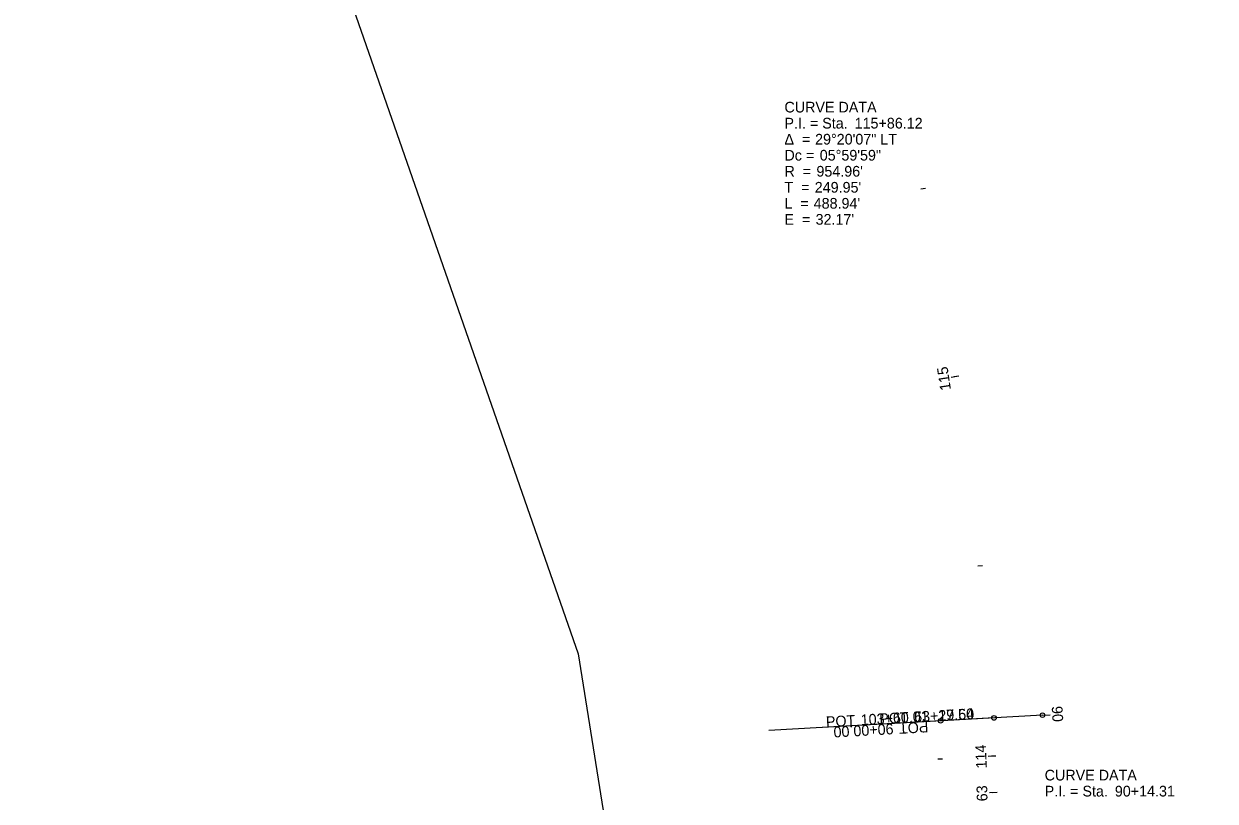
# Model space of a CAD drawing. Extents: x 1564517 to 1565226, y 635740 to 637455.
# Drawn here: x 1564517 to 1564828.9, y 636838.2 to 637041.9 of the extents above; entities that cross this region are included whole.
import ezdxf

# ---------------------------------------------------------------- set-up
doc = ezdxf.new("R2010")
doc.units = 0
for name, color, linetype in [('GK_Drainage_Nodes', 7, 'Continuous'), ('SC_Scratch10', 7, 'Continuous'), ('TX_P_1000', 7, 'Continuous'), ('UT_P_Water', 7, 'Continuous'), ('UT_P_Water_Cells', 7, 'Continuous'), ('UT_X_Electric', 7, 'Continuous'), ('UT_X_Sanitary_Pressure_Line', 7, 'Continuous'), ('UT_X_Water_Cells', 7, 'Continuous')]:
    doc.layers.add(name, color=color, linetype=linetype)

msp = doc.modelspace()

# ---------------------------------------------------------------- linework, layer by layer
at = {"layer": 'TX_P_1000'}
msp.add_line((1564771.02, 636860.06), (1564726.09, 636857.57), dxfattribs=at)
at = {"layer": 'UT_P_Water_Cells'}
for p, q in [((1564761.81, 636949.56), (1564759.83, 636949.26)), ((1564757.04, 636859.29), (1564712.11, 636856.79)), ((1564771.02, 636860.06), (1564726.09, 636857.57)), ((1564771.02, 636860.06), (1564726.09, 636857.57)), ((1564783.7, 636860.77), (1564738.77, 636858.27)), ((1564783.7, 636860.77), (1564785.7, 636860.88)), ((1564771.52, 636850.07), (1564770.32, 636850.02)), ((1564771.82, 636840.48), (1564770.62, 636840.45))]:
    msp.add_line(p, q, dxfattribs=at)
for centre in [(1564757.04, 636859.29), (1564771.02, 636860.06), (1564771.02, 636860.06), (1564783.7, 636860.77)]:
    msp.add_circle(centre, 0.6, dxfattribs=at)
at = {"layer": 'UT_X_Electric'}
msp.add_lwpolyline([(1564682.06, 636752.05), (1564842.01, 636748.56), (1564861.83, 636755.87), (1564842.73, 637279.63), (1564517.04, 637293.63), (1564662.12, 636876.82)], close=True, dxfattribs=at)
at = {"layer": 'UT_X_Sanitary_Pressure_Line'}
for p, q in [((1564761.81, 636949.56), (1564760.62, 636949.38)), ((1564757.04, 636859.29), (1564712.11, 636856.79)), ((1564771.02, 636860.06), (1564726.09, 636857.57)), ((1564771.02, 636860.06), (1564726.09, 636857.57)), ((1564783.7, 636860.77), (1564738.77, 636858.27)), ((1564783.7, 636860.77), (1564785.7, 636860.88))]:
    msp.add_line(p, q, dxfattribs=at)
for centre in [(1564757.04, 636859.29), (1564771.02, 636860.06), (1564771.02, 636860.06), (1564783.7, 636860.77)]:
    msp.add_circle(centre, 0.6, dxfattribs=at)
at = {"layer": 'UT_X_Water_Cells'}
for p, q in [((1564753.06, 636998.78), (1564751.88, 636998.54)), ((1564761.81, 636949.56), (1564759.83, 636949.26)), ((1564767.97, 636899.94), (1564766.77, 636899.83)), ((1564783.7, 636860.77), (1564785.7, 636860.88)), ((1564771.52, 636850.07), (1564769.52, 636849.98)), ((1564757.5, 636849.29), (1564756.3, 636849.24)), ((1564771.82, 636840.48), (1564769.82, 636840.43))]:
    msp.add_line(p, q, dxfattribs=at)
msp.add_circle((1564771.02, 636860.06), 0.6, dxfattribs=at)

# ---------------------------------------------------------------- texts
at = {"layer": 'GK_Drainage_Nodes'}
for s, p in [('CURVE DATA', (1564716.16, 637018.67)), ('P.I. = Sta. ', (1564716.16, 637014.47)), ('115+86.12', (1564734.53, 637014.47)), ('Δ  = ', (1564716.16, 637010.27)), ('29°20\'07" LT', (1564724.18, 637010.27)), ('Dc = ', (1564716.16, 637006.07)), ('05°59\'59"', (1564725.4, 637006.07)), ('R  = ', (1564716.16, 637001.87)), ("954.96'", (1564724.53, 637001.87)), ('T  = ', (1564716.16, 636997.67)), ("249.95'", (1564724.09, 636997.67)), ('L  = ', (1564716.16, 636993.47)), ("488.94'", (1564723.81, 636993.47)), ('E  = ', (1564716.16, 636989.27)), ("32.17'", (1564724.31, 636989.27)), ('CURVE DATA', (1564784.28, 636843.67)), ('P.I. = Sta. ', (1564784.28, 636839.47)), ('90+14.31', (1564802.65, 636839.47))]:
    msp.add_text(s, height=2.8, dxfattribs=at).set_placement(p)
at = {"layer": 'SC_Scratch10'}
for s, p in [('CURVE DATA', (1564716.16, 637018.67)), ('P.I. = Sta. ', (1564716.16, 637014.47)), ('115+86.12', (1564734.53, 637014.47)), ('Δ  = ', (1564716.16, 637010.27)), ('29°20\'07" LT', (1564724.18, 637010.27)), ('Dc = ', (1564716.16, 637006.07)), ('05°59\'59"', (1564725.4, 637006.07)), ('R  = ', (1564716.16, 637001.87)), ("954.96'", (1564724.53, 637001.87)), ('T  = ', (1564716.16, 636997.67)), ("249.95'", (1564724.09, 636997.67)), ('L  = ', (1564716.16, 636993.47)), ("488.94'", (1564723.81, 636993.47)), ('E  = ', (1564716.16, 636989.27)), ("32.17'", (1564724.31, 636989.27)), ('CURVE DATA', (1564784.28, 636843.67)), ('P.I. = Sta. ', (1564784.28, 636839.47)), ('90+14.31', (1564802.65, 636839.47))]:
    msp.add_text(s, height=2.8, dxfattribs=at).set_placement(p)
at = {"layer": 'UT_P_Water'}
for s, p in [('CURVE DATA', (1564716.16, 637018.67)), ('P.I. = Sta. ', (1564716.16, 637014.47)), ('115+86.12', (1564734.53, 637014.47)), ('Δ  = ', (1564716.16, 637010.27)), ('29°20\'07" LT', (1564724.18, 637010.27)), ('Dc = ', (1564716.16, 637006.07)), ('05°59\'59"', (1564725.4, 637006.07)), ('R  = ', (1564716.16, 637001.87)), ("954.96'", (1564724.53, 637001.87)), ('T  = ', (1564716.16, 636997.67)), ("249.95'", (1564724.09, 636997.67)), ('L  = ', (1564716.16, 636993.47)), ("488.94'", (1564723.81, 636993.47)), ('E  = ', (1564716.16, 636989.27)), ("32.17'", (1564724.31, 636989.27)), ('CURVE DATA', (1564784.28, 636843.67)), ('P.I. = Sta. ', (1564784.28, 636839.47)), ('90+14.31', (1564802.65, 636839.47))]:
    msp.add_text(s, height=2.8, dxfattribs=at).set_placement(p)
at = {"layer": 'UT_P_Water_Cells'}
for s, rotation, p in [('115', 98.5774, (1564759.76, 636946.06)), ('63+19.60', 3.1776, (1564750.18, 636858.91)), ('53+27.54', 3.1776, (1564750.18, 636858.91)), ('90', 273.1776, (1564786.12, 636863.1)), ('POT', 3.1776, (1564727.09, 636857.62)), ('103+60.01', 3.1776, (1564736.2, 636858.13)), ('POT', 3.1776, (1564741.07, 636858.4)), ('POT', 3.1776, (1564741.07, 636858.4)), ('90+00.00', 183.1776, (1564744.63, 636858.6)), ('POT', 183.1776, (1564753.75, 636859.1))]:
    msp.add_text(s, height=2.8, rotation=rotation, dxfattribs=at).set_placement(p)
at = {"layer": 'UT_X_Sanitary_Pressure_Line'}
for s, rotation, p in [('63+19.60', 3.1776, (1564750.18, 636858.91)), ('53+27.54', 3.1776, (1564750.18, 636858.91)), ('90', 273.1776, (1564786.12, 636863.1)), ('POT', 3.1776, (1564727.09, 636857.62)), ('103+60.01', 3.1776, (1564736.2, 636858.13)), ('POT', 3.1776, (1564741.07, 636858.4)), ('POT', 3.1776, (1564741.07, 636858.4)), ('90+00.00', 183.1776, (1564744.63, 636858.6)), ('POT', 183.1776, (1564753.75, 636859.1))]:
    msp.add_text(s, height=2.8, rotation=rotation, dxfattribs=at).set_placement(p)
at = {"layer": 'UT_X_Water_Cells'}
for s, rotation, p in [('115', 98.5774, (1564759.76, 636946.06)), ('90', 273.1776, (1564786.12, 636863.1)), ('114', 92.5776, (1564769.16, 636846.87)), ('63', 91.5139, (1564769.33, 636838.24))]:
    msp.add_text(s, height=2.8, rotation=rotation, dxfattribs=at).set_placement(p)

doc.saveas('drawing.dxf')
